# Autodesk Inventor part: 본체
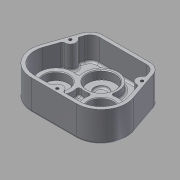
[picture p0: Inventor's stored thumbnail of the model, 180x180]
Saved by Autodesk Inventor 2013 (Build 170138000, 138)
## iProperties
Created: 2014-12
Part Number: 본체
Material: 알루미늄 6061
Document SubType Name: Modeling
Designer: Administrator
Density: 2.71 g/cm^3
Mass: 613.43 g
Surface Area: 665.343 cm^2
Volume: 226.358 cm^3
Author: Administrator
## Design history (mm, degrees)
sketch "스케치1"
  geometry: L1 (-34.162, 36)-(34.162, 36); L2 (0, 0)-(46, 0); L3 (0, 0)-(32.527, -32.527); L4 (0, 0)-(-32.527, -32.527); L5 (-32.527, -68.527)-(32.527, -68.527); L6 (51.181, 23.862)-(66.565, -20.803); L7 (-51.181, 23.862)-(-66.565, -20.803); A1 r 46 centre (0, 0) between (46, 0) and (32.527, -32.527); A2 r 36 centre (32.527, -32.527) between (32.527, -68.527) and (66.565, -20.803); A3 r 36 centre (-32.527, -32.527) between (-66.565, -20.803) and (-32.527, -68.527); A4 r 18 centre (-34.162, 18) between (-34.162, 36) and (-51.181, 23.862); A5 r 18 centre (34.162, 18) between (51.181, 23.862) and (34.162, 36); 3 further points
  constraints: 14 end point, 11 point on circle, 8 tangent, 5 centre point, 4 point on line, 3 coincident, 1 equal radius, 1 horizontal, 1 parallel, 1 perpendicular
  dimensions: "d1" = 94 distance of point (-47, 36) point (47, 36); "d3" = 47 horizontal distance of point (0, 0) point (47, 36); "d4" = 92 diameter of A1; "d5" = 36 distance from line of point (0, 0) L1; "d6" = 45 deg angle of L3 L2; "d8" = 72 diameter of A3; "d9" = 18 radius of A4; "d10" = 36 radius of A2
extrude "돌출1" new body sketch "스케치1" distance "d11" = 44; taper "d12" = 0 deg
sketch "스케치2"
  geometry: L1 (-32.527, -68.527)-(32.527, -68.527) reference; L2 (66.565, -20.803)-(51.181, 23.862) reference; L3 (-32.527, -68.527)-(32.527, -68.527) reference; L4 (66.565, -20.803)-(51.181, 23.862) reference; L5 (34.162, 36)-(-34.162, 36) reference; L6 (-51.181, 23.862)-(-66.565, -20.803) reference; L7 (-36.272, -63.527)-(32.527, -63.527); L8 (-34.162, 31)-(34.162, 31); L9 (61.837, -22.432)-(46.453, 22.233); L10 (-46.453, 22.233)-(-61.837, -22.432); A1 r 36 centre (32.527, -32.527) between (32.527, -68.527) and (66.565, -20.803) reference; A2 r 18 centre (-34.162, 18) between (-34.162, 36) and (-51.181, 23.862) reference; A3 r 36 centre (-32.527, -32.527) between (-66.565, -20.803) and (-32.527, -68.527) reference; A4 r 36 centre (32.527, -32.527) between (32.527, -68.527) and (66.565, -20.803) reference; A5 r 18 centre (34.162, 18) between (51.181, 23.862) and (34.162, 36) reference; A6 r 18 centre (-34.162, 18) between (-34.162, 36) and (-51.181, 23.862) reference; A7 r 36 centre (-32.527, -32.527) between (-66.565, -20.803) and (-32.527, -68.527) reference; A8 r 13 centre (-34.162, 18) between (-34.162, 31) and (-46.453, 22.233); A9 r 13 centre (34.162, 18) between (46.453, 22.233) and (34.162, 31); A10 r 31 centre (32.527, -32.527) between (32.527, -63.527) and (61.837, -22.432); A11 r 31 centre (-32.527, -32.527) between (-61.837, -22.432) and (-32.527, -63.527); 1 further point
  constraints: 8 end point, 8 point on circle, 7 tangent, 4 centre point, 4 coincident, 1 parallel, 1 point on line
  dimensions: "d17" = 13 radius of A8; "d18" = 13 radius of A9; "d19" = 31 radius of A10; "d20" = 31 radius of A11
extrude "돌출2" cut sketch "스케치2" distance "d21" = 34; taper "d22" = 0 deg
sketch "스케치3"
  geometry: L1 (-61.837, -22.432)-(-46.453, 22.233) reference; L2 (32.527, -63.527)-(-32.527, -63.527) reference; L3 (46.453, 22.233)-(61.837, -22.432) reference; L4 (-34.162, 31)-(34.162, 31) reference; L5 (-49.095, 14.564)-(-54.305, -0.564); L6 (-8, -63.527)-(8, -63.527); L7 (54.305, -0.564)-(49.095, 14.564); A1 r 8 centre (51.7, 7) between (49.095, 14.564) and (54.305, -0.564); A2 r 8 centre (-51.7, 7) between (-54.305, -0.564) and (-49.095, 14.564); A3 r 8 centre (0, -63.527) between (8, -63.527) and (-8, -63.527); 1 further point
  constraints: 8 point on line, 6 end point, 6 point on circle, 3 centre point, 3 collinear, 1 midpoint
  dimensions: "d23" = 8 radius of A1; "d24" = 24 distance from line of A1.centre L4; "d25" = 8 radius of A2; "d26" = 24 distance from line of A2.centre L4; "d27" = 8 radius of A3
extrude "돌출3" join sketch "스케치3" distance "d28" = 34; taper "d29" = 0 deg
sketch "스케치4"
  geometry: A1 r 8 centre (-51.7, 7) between (-54.305, -0.564) and (-49.095, 14.564) reference; A2 r 8 centre (51.7, 7) between (49.095, 14.564) and (54.305, -0.564) reference; A3 r 8 centre (0, -63.527) between (8, -63.527) and (-8, -63.527) reference; 4 further points
  constraints: 3 coincident
hole "구멍1" sketch "스케치4" at (-51.7, 7), (0, -63.527), (51.7, 7) diameter "d30" = 4.134; stored, may be unused: countersink angle "d34" = 82 deg, drill point angle "d36" = 118 deg; dims "d31" = 20, "d32" = 3.023, "d33" = 2, "d35" = 23
sketch "스케치5"
  geometry: C1 r 24 at (0, 0); C2 r 24 at (-32.527, -32.527); C3 r 24 at (32.527, -32.527); A1 r 31 centre (-32.527, -32.527) between (-61.837, -22.432) and (-32.527, -63.527) reference; A2 r 31 centre (32.527, -32.527) between (32.527, -63.527) and (61.837, -22.432) reference; 1 further point
  constraints: 3 centre point, 3 coincident
  dimensions: "d37" = 48 diameter of C1; "d38" = 48 diameter of C2; "d39" = 48 diameter of C3
extrude "돌출4" join sketch "스케치5" distance "d40" = 11; taper "d41" = 0 deg
sketch "스케치6"
  geometry: C1 r 20 at (0, 0); A1 r 24 centre (0, 0) between (21.111, -11.416) and (-21.111, -11.416) reference
  constraints: 1 centre point, 1 coincident
  dimensions: "d42" = 40 diameter of C1
extrude "돌출5" cut sketch "스케치6" distance "d43" = 12; taper "d44" = 0 deg
sketch "스케치7"
  geometry: C1 r 20 at (0, 0) reference; C2 r 10 at (0, 0)
  constraints: 1 centre point, 1 coincident
  dimensions: "d45" = 20 diameter of C2
extrude "돌출6" cut sketch "스케치7" distance "d46" = 3; taper "d47" = 0 deg
sketch "스케치8"
  geometry: C1 r 17.5 at (-32.527, -32.527); C2 r 17.5 at (32.527, -32.527); A1 r 24 centre (32.527, -32.527) between (11.416, -21.111) and (21.111, -11.416) reference; A2 r 24 centre (-32.527, -32.527) between (-21.111, -11.416) and (-11.416, -21.111) reference
  constraints: 2 centre point, 2 coincident
  dimensions: "d48" = 35 diameter of C1; "d49" = 35 diameter of C2
extrude "돌출7" cut sketch "스케치8" distance "d50" = 11; taper "d51" = 0 deg
sketch "스케치9"
  geometry: C1 r 7.75 at (-32.527, -32.527); C2 r 7.75 at (32.527, -32.527); A1 r 31 centre (-32.527, -32.527) between (-61.837, -22.432) and (-32.527, -63.527) reference; A2 r 31 centre (32.527, -32.527) between (32.527, -63.527) and (61.837, -22.432) reference
  constraints: 2 centre point, 2 coincident
  dimensions: "d52" = 15.5 diameter of C1; "d53" = 15.5 diameter of C2
extrude "돌출8" cut sketch "스케치9" distance "d54" = 10; taper "d55" = 0 deg
sketch "스케치10"
  geometry: C1 r 7.75 at (32.527, -32.527) reference; C2 r 7.75 at (-32.527, -32.527) reference; C3 r 20 at (-32.527, -32.527); C4 r 20 at (32.527, -32.527); A1 r 36 centre (32.527, -32.527) between (32.527, -68.527) and (66.565, -20.803) reference; A2 r 36 centre (-32.527, -32.527) between (-66.565, -20.803) and (-32.527, -68.527) reference; 1 further point
  constraints: 2 centre point, 2 coincident
  dimensions: "d56" = 40 diameter of C3; "d57" = 40 diameter of C4
extrude "돌출9" join sketch "스케치10" distance "d58" = 7; taper "d59" = -10 deg
sketch "스케치11"
  geometry: L1 (34.162, 36)-(-34.162, 36) reference; 2 further points
  constraints: 1 vertical alignment, 1 other
  dimensions: "d63" = 30 distance from line of point (0, 6) L1
feature "엠보싱1" sketch "스케치11" dims "d1" = 94, "d3" = 47, "d4" = 92, "d5" = 36, "d6" = 45 deg, "d8" = 72, "d9" = 18, "d10" = 36, "d61" = 1, "d62" = 0
fillet "모깎기1" dims "d64" = 0.3
sketch "스케치12"
  geometry: C1 r 18.766 at (0, 0) reference; C2 r 18.766 at (65.054, 0) reference; C3 r 20 at (65.054, 0) reference; C4 r 15 at (0, 0); C5 r 15 at (65.054, 0); 1 further point
  constraints: 2 centre point, 2 coincident
  dimensions: "d65" = 30 diameter of C4; "d66" = 30 diameter of C5
extrude "돌출10" cut sketch "스케치12" distance "d67" = 7; taper "d68" = 0 deg
fillet "모깎기2" dims "d69" = 0.1
fillet "모깎기3" dims "d70" = 3
fillet "모깎기4" dims "d71" = 3
fillet "모깎기5" dims "d72" = 3
fillet "모깎기6" dims "d73" = 3
fillet "모깎기7" dims "d74" = 3
chamfer "모따기1" distance "d75" = 1; stored, may be unused: second distance "d76" = 2, angle "d77" = 45 deg
fillet "모깎기8" dims "d78" = 3
fillet "모깎기9" dims "d79" = 0.3
node "솔리드1"
node "투영된 루프1"
node "투영된 루프2"
